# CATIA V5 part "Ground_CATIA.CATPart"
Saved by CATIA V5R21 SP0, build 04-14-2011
Part number: Ground
Bounding box of the stored display mesh (mm): x -130 to 130, y -15 to 15, z 0 to 10
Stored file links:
  C:\Users\DHARUN\Documents\Codex\2026-11-26\task-2-structural-simulation-fea-perform\outputs\task3_slider_crank\Ground_CATIA.CATPart
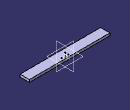
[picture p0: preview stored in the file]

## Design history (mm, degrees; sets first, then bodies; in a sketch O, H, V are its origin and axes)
Set1 "KinematicReferences"
  Point1 "O": (0, 0, 0)
  Point2 "Z": (0, 0, 10)
  Point3 "X": (10, 0, 0)
  Point4 "Y": (0, 10, 0)
  Line1: type PtPt, FirstPoint Point1, SecondPoint Point2
  Plane1: type 3Points, Element1 Point1, Element2 Point3, Element3 Point4
  Point5 "GuideStart": (-10, 0, 0)
  Point6 "GuideEnd": (10, 0, 0)
  Line2: type PtPt, FirstPoint Point5, SecondPoint Point6
  Plane2: type 3Points, Element1 Point1, Element2 Point3, Element3 Point4
Body1 (main body)
  Sketch1 on xy-plane, origin (0, 0, 0), H (1, 0, 0), V (0, 1, 0)
    line L1 (-130, -15) -> (130, -15)
    line L2 (130, -15) -> (130, 15)
    line L3 (130, 15) -> (-130, 15)
    line L4 (-130, 15) -> (-130, -15)
    point P1 (-130, -15)
    point P2 (130, -15)
    point P3 (130, -15)
    point P4 (130, 15)
    point P5 (130, 15)
    point P6 (-130, 15)
    point P7 (-130, 15)
    point P8 (-130, -15)
    coincidence: P1 P8, P2 P3, P4 P5, P6 P7
  Pad1 "Ground_Solid": profile Sketch1, direction (0, 0, 1), length 8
